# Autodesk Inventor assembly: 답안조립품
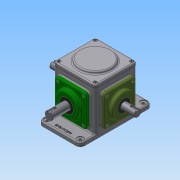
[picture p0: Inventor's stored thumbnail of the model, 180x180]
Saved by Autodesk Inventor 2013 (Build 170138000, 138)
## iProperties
Created: 2019-04
Part Number: 답안조립품
Document SubType Name: Assembly
Designer: Administrator
Author: Administrator
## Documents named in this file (16)
- C:\Users\Administrator\Desktop\390407V1019\답안조립품.iam
- C:\Users\Administrator\Desktop\390407V1019\공용부품\본체.ipt
- C:\Users\Administrator\Desktop\390407V1019\공용부품\개스킷.ipt
- C:\Users\Administrator\Desktop\390407V1019\공용부품\메인베벨기어.ipt
- C:\Users\Administrator\Desktop\390407V1019\공용부품\메인축.ipt
- C:\Users\Administrator\Desktop\390407V1019\공용부품\메인커버.ipt
- C:\Users\Administrator\Desktop\390407V1019\공용부품\베어링 6203.ipt
- C:\Users\Administrator\Desktop\390407V1019\공용부품\베어링 6204.ipt
- C:\Users\Administrator\Desktop\390407V1019\공용부품\볼트 M4.ipt
- C:\Users\Administrator\Desktop\390407V1019\공용부품\상부커버.ipt
- C:\Users\Administrator\Desktop\390407V1019\공용부품\서브베벨기어.ipt
- C:\Users\Administrator\Desktop\390407V1019\공용부품\서브축.ipt
- C:\Users\Administrator\Desktop\390407V1019\공용부품\서브커버.ipt
- C:\Users\Administrator\Desktop\390407V1019\공용부품\오일 실 17 32 8.ipt
- C:\Users\Administrator\Desktop\390407V1019\공용부품\오일 실 20 35 8.ipt
- C:\Users\Administrator\Desktop\390407V1019\공용부품\키 4x4.ipt
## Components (1 placed, 1 different names)
1. 개스킷:1
